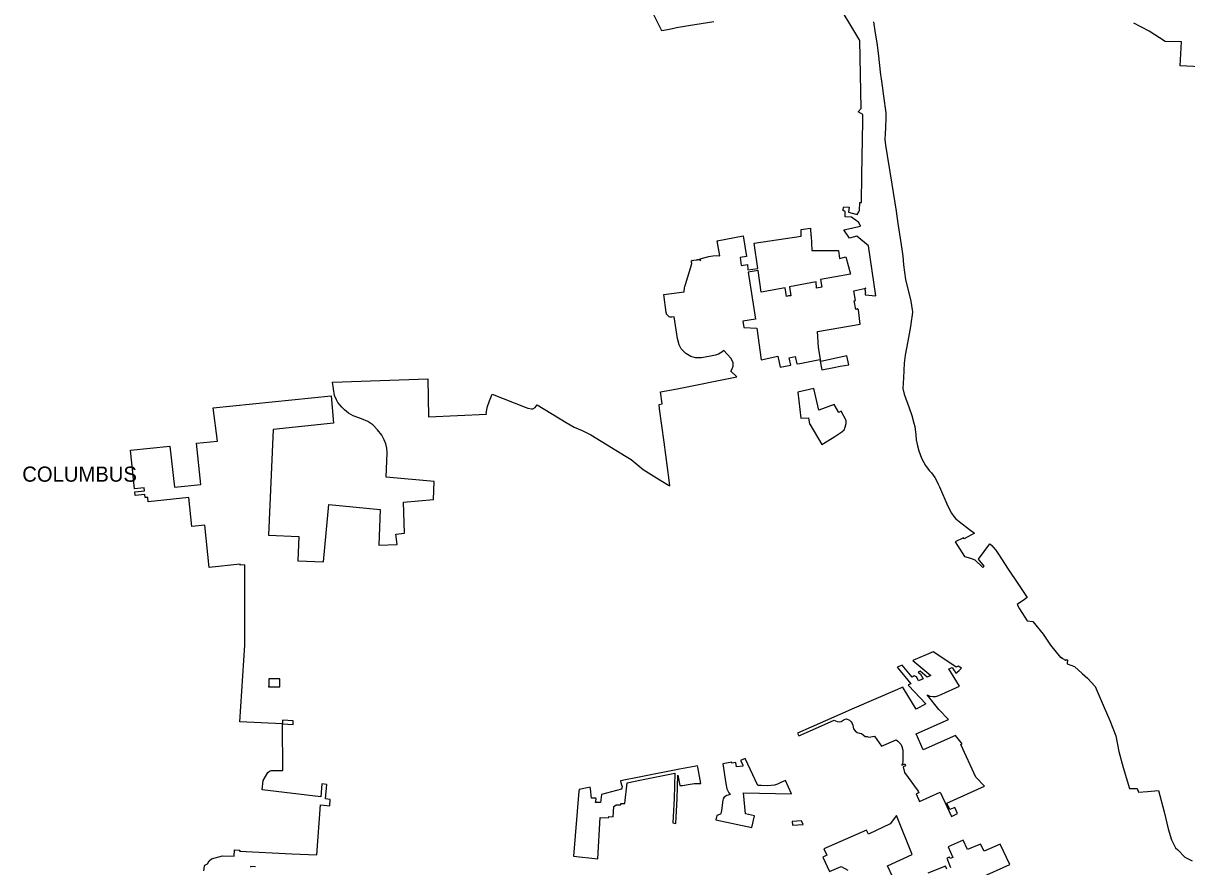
# Model space of a CAD drawing. Extents: x 1597222 to 1925846, y 496284 to 911751.
# Drawn here: x 1773508 to 1811969, y 720472 to 748344 of the extents above; entities that cross this region are included whole.
import ezdxf

# ---------------------------------------------------------------- set-up
doc = ezdxf.new("R2010")
doc.units = 0
doc.layers.add('GM_X_Corporation', color=7, linetype='Continuous')
doc.layers.add('GM_X_Corporation_Text', color=7, linetype='Continuous')

msp = doc.modelspace()

# ---------------------------------------------------------------- linework, layer by layer
at = {"layer": 'GM_X_Corporation'}
for points in [[(1779482, 720334), (1779503, 720485), (1779513, 720523), (1779596, 720571), (1779653, 720669), (1779729, 720727), (1780099, 720836), (1780477, 720818), (1780488, 721032), (1780662, 721023), (1780661, 720988), (1782384, 720903), (1783212, 720865), (1783332, 722520), (1783639, 722485), (1783658, 722695), (1783499, 722716), (1783542, 723193), (1783379, 723209), (1783341, 722779), (1781405, 723011), (1781443, 723326), (1781588, 723590), (1781646, 723634), (1781714, 723651), (1782093, 723654), (1782076, 725199), (1780670, 725260), (1780827, 727797), (1780837, 730452), (1780678, 730440), (1780677, 730470), (1779654, 730364), (1779507, 731764), (1779085, 731719), (1778983, 732673), (1777637, 732530), (1777622, 732677), (1777536, 732668), (1777525, 732768), (1777207, 732734), (1777194, 732855), (1777513, 732889), (1777502, 732988), (1777184, 732955), (1777049, 734232), (1778358, 734372), (1778503, 733014), (1779377, 733108), (1779233, 734463), (1779925, 734537), (1779785, 735635), (1783690, 736031), (1783761, 735131), (1781764, 734921), (1781619, 731424), (1782618, 731382), (1782584, 730581), (1783429, 730546), (1783614, 732439), (1785305, 732274), (1785265, 731095), (1785864, 731116), (1785829, 731462), (1786109, 731495), (1786081, 732516), (1787068, 732606), (1787086, 733205), (1785506, 733341), (1785537, 734146), (1785530, 734302), (1785490, 734451), (1785435, 734577), (1785357, 734729), (1785223, 734911), (1785067, 735075), (1784895, 735179), (1784693, 735269), (1784413, 735373), (1784257, 735460), (1784128, 735574), (1784041, 735657), (1783980, 735727), (1783903, 735814), (1783857, 735903), (1783797, 736047), (1783729, 736484), (1786883, 736592), (1786907, 735343), (1788818, 735431), (1788815, 735475), (1788820, 735508), (1788829, 735580), (1788851, 735682), (1788920, 735864), (1789012, 736092), (1790098, 735655), (1790189, 735623), (1790305, 735599), (1790352, 735602), (1790432, 735643), (1790492, 735739), (1791458, 735151), (1791718, 734992), (1791982, 734884), (1792270, 734745), (1793442, 734023), (1793602, 733927), (1793997, 733597), (1794437, 733326), (1794832, 733084), (1794885, 733054), (1794861, 733242), (1794699, 734497), (1794545, 735602), (1794525, 735745), (1794624, 735763), (1794570, 736161), (1795072, 736254), (1797098, 736664), (1796898, 736851), (1796940, 736926), (1796970, 737010), (1796975, 737119), (1796947, 737199), (1796900, 737273), (1796669, 737527), (1796601, 737474), (1796487, 737408), (1796389, 737373), (1796226, 737341), (1795929, 737286), (1795732, 737292), (1795571, 737335), (1795407, 737432), (1795257, 737587), (1795185, 737723), (1795137, 737924), (1795029, 738645), (1794951, 738634), (1794915, 738633), (1794889, 738637), (1794863, 738646), (1794833, 738663), (1794810, 738682), (1794791, 738704), (1794776, 738730), (1794767, 738751), (1794761, 738782), (1794687, 739379), (1794932, 739413), (1795353, 739472), (1795356, 739509), (1795364, 739564), (1795371, 739604), (1795380, 739643), (1795389, 739677), (1795400, 739714), (1795598, 740361), (1795600, 740370), (1795602, 740377), (1795603, 740384), (1795604, 740394), (1795605, 740401), (1795605, 740409), (1795604, 740415), (1795603, 740425), (1795596, 740483), (1795595, 740488), (1795593, 740491), (1795622, 740496), (1795614, 740501), (1795603, 740504), (1795756, 740523), (1795769, 740526), (1795782, 740529), (1795795, 740531), (1795811, 740534), (1795843, 740540), (1795853, 740541), (1795862, 740540), (1795869, 740537), (1795876, 740533), (1795883, 740527), (1795887, 740521), (1795889, 740516), (1795892, 740494), (1795895, 740520), (1795894, 740530), (1795892, 740542), (1795888, 740563), (1796176, 740637), (1796307, 740663), (1796408, 740671), (1796532, 740659), (1796442, 741158), (1797302, 741323), (1797412, 740638), (1797207, 740606), (1797242, 740342), (1797444, 740374), (1797459, 740191), (1797786, 740238), (1797664, 741078), (1799228, 741305), (1799220, 741530), (1799534, 741576), (1799542, 741316), (1799558, 741318), (1799575, 740830), (1800457, 740830), (1800493, 740571), (1800699, 740622), (1800850, 740057), (1799860, 739872), (1799911, 739627), (1799731, 739593), (1799723, 739796), (1798839, 739630), (1798886, 739338), (1798799, 739334), (1798737, 739318), (1798692, 739605), (1797903, 739457), (1797796, 740170), (1797469, 740123), (1797713, 738565), (1797296, 738495), (1797323, 738291), (1797759, 738271), (1797898, 737226), (1798449, 737341), (1798524, 736975), (1798882, 737045), (1798827, 737288), (1799026, 737330), (1799082, 737088), (1799179, 737105), (1799836, 737231), (1799906, 736887), (1800305, 736970), (1800508, 737011), (1800801, 737062), (1800735, 737351), (1799874, 737168), (1799795, 737644), (1799761, 738159), (1801173, 738406), (1801119, 738880), (1801089, 738921), (1801071, 738909), (1801032, 738885), (1800975, 739174), (1801024, 739183), (1800963, 739506), (1801356, 739592), (1801351, 739589), (1801346, 739585), (1801343, 739582), (1801339, 739577), (1801335, 739571), (1801333, 739567), (1801331, 739562), (1801330, 739557), (1801329, 739549), (1801329, 739546), (1801330, 739540), (1801331, 739535), (1801332, 739530), (1801335, 739524), (1801342, 739514), (1801343, 739495), (1801345, 739462), (1801344, 739422), (1801342, 739404), (1801341, 739386), (1801338, 739365), (1801694, 739338), (1801449, 740993), (1801066, 741306), (1800821, 741241), (1800636, 741516), (1801179, 741642), (1801130, 741758), (1800882, 741940), (1800674, 741946), (1800674, 742111), (1800596, 742166), (1800636, 742276), (1800810, 742267), (1800786, 742107), (1801071, 742020), (1801125, 742113), (1801155, 742156), (1801160, 742422), (1801214, 742421), (1801229, 743323), (1801259, 745100), (1801263, 745329), (1801105, 745419), (1801209, 745526), (1801161, 747779), (1800318, 749198)], [(1796340, 748394), (1795502, 748255), (1795107, 748192), (1794974, 748159), (1794804, 748124), (1794616, 748095), (1794574, 748180), (1794147, 749043)], [(1801614, 748387), (1801674, 748018), (1801725, 747703), (1801772, 747359), (1801849, 746636), (1801866, 746504), (1801900, 746273), (1801946, 745930), (1802019, 745382), (1802026, 745240), (1802006, 744894), (1801995, 744699), (1801990, 744508), (1802010, 744316), (1802068, 743972), (1802151, 743437), (1802219, 743032), (1802361, 742140), (1802422, 741731), (1802510, 741161), (1802552, 740884), (1802579, 740653), (1802606, 740359), (1802669, 739874), (1802844, 739158), (1802892, 738875), (1802901, 738809), (1802896, 738710), (1802860, 738491), (1802839, 738324), (1802746, 737839), (1802664, 737376), (1802630, 737112), (1802604, 736629), (1802584, 736279), (1802630, 736088), (1802792, 735637), (1802877, 735381), (1802950, 735133), (1802983, 735015), (1803009, 734748), (1803029, 734574), (1803069, 734376), (1803118, 734213), (1803153, 734096), (1803206, 733969), (1803274, 733830), (1803337, 733732), (1803368, 733683), (1803458, 733568), (1803531, 733484), (1803645, 733338), (1803723, 733195), (1803753, 733119), (1803795, 733020), (1804075, 732390), (1804195, 732156), (1804274, 732048), (1804339, 731973), (1804443, 731878), (1804787, 731620), (1804948, 731499), (1804614, 731308), (1804591, 731344), (1804313, 731207), (1804627, 730720), (1804825, 730673), (1804968, 730609), (1805226, 730365), (1805269, 730409), (1805089, 730640), (1805465, 731142), (1805524, 731089), (1805581, 731025), (1805656, 730934), (1805745, 730801), (1805840, 730646), (1806062, 730307), (1806384, 729832), (1806697, 729372), (1806601, 729307), (1806360, 729138), (1806439, 728996), (1806691, 728596), (1806883, 728578), (1807225, 728152), (1807469, 727788), (1807801, 727389), (1807816, 727402), (1807845, 727362), (1807980, 727287), (1807988, 727317), (1808025, 727309), (1808018, 727171), (1808260, 727092), (1808508, 726862), (1808692, 726704), (1808938, 726426), (1809211, 725807), (1809429, 725299), (1809629, 724796), (1809722, 724284), (1809870, 723756), (1810082, 723060), (1810294, 723056), (1810333, 723056), (1810379, 722934), (1810677, 722954), (1811035, 722989), (1811218, 722284), (1811356, 721725), (1811468, 721358), (1811594, 721101), (1811670, 721025), (1811908, 720792), (1812146, 720663)], [(1814606, 746798), (1811751, 746937), (1811795, 747728), (1811257, 747739), (1810722, 748085), (1810221, 748346)], [(1802243, 720146), (1802079, 720503), (1802893, 720878), (1802379, 722159), (1802167, 721888), (1801451, 721549), (1801388, 721683), (1799970, 721058), (1800069, 720849), (1799943, 720789), (1800164, 720310), (1800548, 720480), (1800769, 720362)], [(1805136, 720108), (1806120, 720545), (1805802, 721212), (1805274, 720981), (1805155, 721218), (1804719, 721045), (1804578, 721352), (1804084, 721129), (1804241, 720774), (1804147, 720740), (1804128, 720786), (1804034, 720749), (1804157, 720443)], [(1781185, 720468), (1781015, 720477), (1781014, 720457)], [(1804040, 720392), (1803991, 720491), (1803408, 720261)]]:
    msp.add_lwpolyline(points, dxfattribs=at)
for points in [[(1799215, 735290), (1799463, 735307), (1799493, 735096), (1799508, 735100), (1799905, 734427), (1799964, 734461), (1800338, 734694), (1800572, 734842), (1800640, 734911), (1800676, 734997), (1800706, 735114), (1800712, 735217), (1800549, 735530), (1800463, 735480), (1800309, 735744), (1799811, 735556), (1799640, 736275), (1799108, 736159)], [(1806697, 729372), (1806697, 729372), (1806697, 729372)], [(1804269, 727118), (1803581, 727578), (1802912, 727289), (1803504, 726787), (1803391, 726740), (1803159, 726936), (1803091, 726899), (1803168, 726833), (1803260, 726683), (1803105, 726615), (1803068, 726696), (1803031, 726743), (1802960, 726779), (1802890, 726733), (1802562, 727136), (1802399, 727064), (1802848, 726520), (1802758, 726480), (1802776, 726461), (1803345, 725854), (1803020, 725680), (1802596, 726381), (1802583, 726404), (1802333, 726296), (1800972, 725711), (1799556, 725082), (1799105, 724884), (1799126, 724839), (1799147, 724793), (1799596, 724991), (1800317, 725311), (1800357, 725296), (1800415, 725275), (1800477, 725260), (1800549, 725271), (1800614, 725320), (1800674, 725350), (1800726, 725355), (1800816, 725320), (1800879, 725257), (1800904, 725202), (1800926, 725148), (1800939, 725086), (1800952, 725025), (1801011, 724958), (1801078, 724905), (1801154, 724884), (1801220, 724869), (1801271, 724831), (1801337, 724778), (1801405, 724775), (1801457, 724750), (1801645, 724786), (1801878, 724461), (1802359, 724665), (1802413, 724619), (1802481, 724555), (1802518, 724521), (1802548, 724450), (1802586, 724326), (1802582, 724235), (1802582, 724150), (1802579, 724143), (1802580, 724115), (1802579, 724081), (1802582, 724046), (1802588, 724010), (1802580, 723973), (1802579, 723934), (1802578, 723897), (1802575, 723882), (1802547, 723831), (1802646, 723874), (1802669, 723808), (1802592, 723774), (1802634, 723583), (1803086, 722971), (1803112, 722916), (1803021, 722875), (1803135, 722625), (1803820, 722936), (1804188, 722128), (1804390, 722226), (1804301, 722433), (1804132, 722359), (1804042, 722568), (1805284, 723129), (1804994, 723431), (1804501, 724514), (1804547, 724535), (1804327, 724807), (1803253, 724332), (1803020, 724858), (1804094, 725333), (1803777, 725666), (1803389, 726153), (1803480, 726112), (1803579, 726094), (1803680, 726098), (1803779, 726131), (1803870, 726171), (1804455, 726441), (1804105, 727014), (1804210, 727057), (1804268, 726964), (1804276, 726968), (1804337, 726867), (1804434, 726946), (1804477, 726990), (1804500, 727009), (1804523, 727028), (1804418, 727095), (1804352, 727064)], [(1781627, 726679), (1781629, 726439), (1781609, 726439), (1781610, 726413), (1781990, 726415), (1781985, 726679)], [(1782080, 725319), (1782082, 725199), (1782435, 725176), (1782434, 725297)], [(1796405, 722022), (1797595, 721763), (1797680, 722153), (1797378, 722219), (1797315, 722917), (1798901, 722883), (1798705, 723318), (1798550, 723251), (1798436, 723202), (1798339, 723170), (1798236, 723154), (1798108, 723149), (1797905, 723151), (1797795, 723153), (1797377, 724049), (1797222, 723986), (1797299, 723834), (1797290, 723790), (1797083, 723774), (1797062, 723915), (1796936, 723895), (1796932, 723925), (1796628, 723877), (1796729, 723219), (1796768, 723051), (1796832, 722909), (1796879, 722854), (1796812, 722837), (1796762, 722824), (1796680, 722772), (1796646, 722712), (1796634, 722671), (1796584, 722332), (1796567, 722234), (1796552, 722212), (1796525, 722192), (1796436, 722165)], [(1795810, 723757), (1795801, 723806), (1795690, 723787), (1795206, 723698), (1793923, 723445), (1793248, 723305), (1793264, 723257), (1793289, 723176), (1793305, 723123), (1793300, 723070), (1793288, 723035), (1792624, 722857), (1792592, 722594), (1792421, 722594), (1792441, 722701), (1792438, 722740), (1792289, 722732), (1792257, 723051), (1792253, 723101), (1792146, 723079), (1791880, 723024), (1791875, 722972), (1791697, 720821), (1792501, 720727), (1792577, 722098), (1792857, 722083), (1792860, 722133), (1793009, 722124), (1793028, 722458), (1793110, 722515), (1793260, 722514), (1793260, 722564), (1793390, 722564), (1793470, 723248), (1793943, 723347), (1795049, 723565), (1795020, 722726), (1794982, 721923), (1795081, 721902), (1795120, 722722), (1795146, 723493), (1795208, 723157), (1795240, 723158), (1795296, 723161), (1795362, 723169), (1795422, 723176), (1795492, 723187), (1795550, 723196), (1795630, 723211), (1795691, 723218), (1795745, 723224), (1795819, 723225), (1795893, 723222), (1795908, 723220)], [(1798926, 721968), (1798934, 721848), (1799285, 721870), (1799232, 721987)]]:
    msp.add_lwpolyline(points, close=True, dxfattribs=at)

# ---------------------------------------------------------------- texts
at = {"layer": 'GM_X_Corporation_Text'}
msp.add_text('COLUMBUS', height=500, rotation=0, dxfattribs=at).set_placement((1773474, 733195))

doc.saveas('drawing.dxf')
